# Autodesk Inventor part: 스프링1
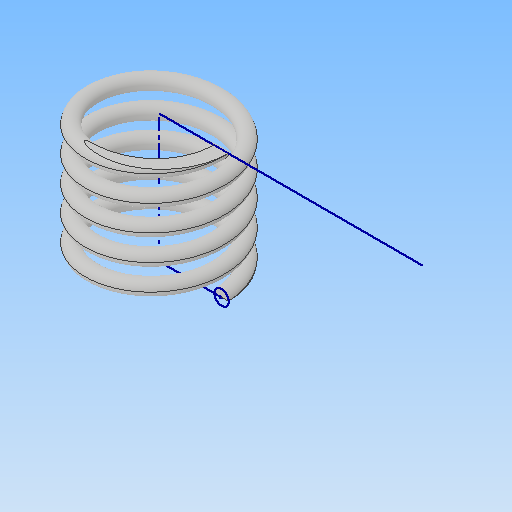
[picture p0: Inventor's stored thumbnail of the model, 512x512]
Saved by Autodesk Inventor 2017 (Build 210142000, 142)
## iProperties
Part Number: 스프링1
Material: 일반
Document SubType Name: Modeling
Designer: MRC
Density: 1 g/cm^3
Appearance: 기본값
Mass: 0.819704 g
Surface Area: 16.7052 cm^2
Volume: 0.819704 cm^3
Author: MRC
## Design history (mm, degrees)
sketch "스케치1"
  geometry: L1 (0, 0)-(0, 17.5); L2 (0, 0)-(8.5, 0); L3 (0, 17.5)-(36.027, 17.5); C1 r 1 at (8.5, 0)
  constraints: 6 end point, 2 horizontal, 1 centre point, 1 coincident, 1 vertical
  dimensions: "d0" = 17.5 distance of L1.start L1.end (derived); "d2" = 2 diameter of C1; "d3" = 17 diameter of L2.end L1
feature "코일1" pitch "d4" = 10; turns "d6" = 5; dims "d5" = 17.5 (= d0), "d7" = 0, angle "d8" = 90 deg, angle "d9" = 90 deg, "d10" = 0, "d11" = 0
sketch "스케치2"
  geometry: L1 (17.5, 10)-(0, 10); L2 (0, 10)-(0, -10); L3 (0, -10)-(17.5, -10); L4 (17.5, -10)-(17.5, 10); 2 further points
  constraints: 8 end point, 2 parallel, 1 coincident, 1 horizontal, 1 midpoint, 1 perpendicular
  dimensions: "d12" = 20 distance of L3.end L1.start; "d13" = 17.5 distance of L2.end L3.end (= d0)
extrude "돌출1" sketch "스케치2" stored distance "d14" = 0; taper "d15" = 0 deg
node "솔리드1"
